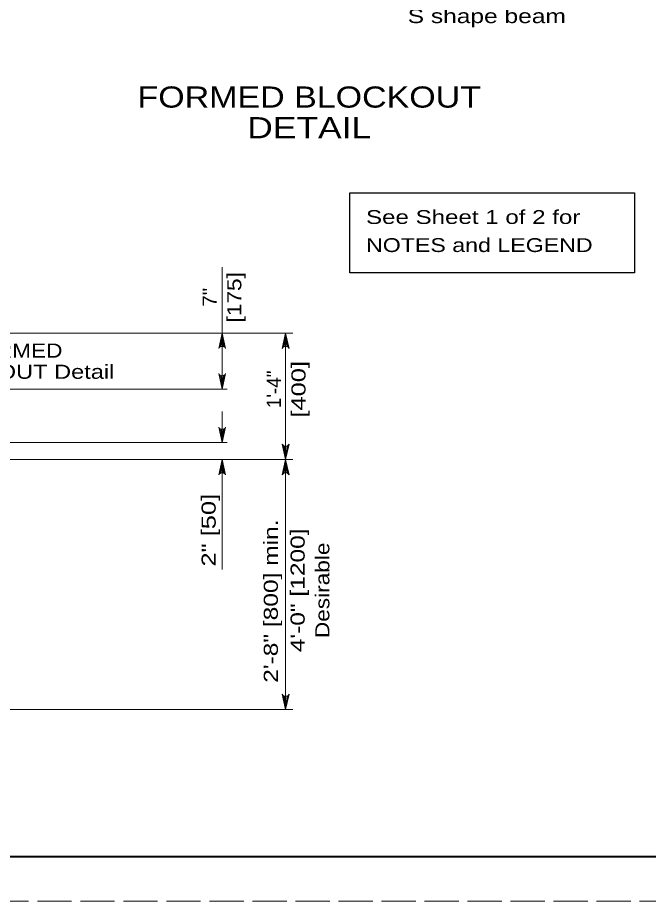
# Model space of a CAD drawing. Extents: x -1431.2 to -1397.2, y -1045.1 to -1001.1.
# Drawn here: x -1417.92 to -1410.82, y -1045.08 to -1035.13 of the extents above; entities that cross this region are included whole.
import ezdxf
from ezdxf.enums import TextEntityAlignment as Align

# ---------------------------------------------------------------- set-up
doc = ezdxf.new("R2010")
doc.units = 0
doc.header["$LTSCALE"] = 0.064
doc.linetypes.add('LONG_DASHED', pattern=[7.5, 6, -1.5])
doc.layers.add('1', color=7, linetype='Continuous', lineweight=13)

msp = doc.modelspace()

# ---------------------------------------------------------------- linework, layer by layer
at = {"layer": '1'}
for p, q in [((-1415.61583, -1039.31042), (-1415.61583, -1037.93983)), ((-1420.55817, -1038.68067), (-1414.82, -1038.68067)), ((-1415.61583, -1038.68067), (-1419.337, -1038.68067)), ((-1415.64275, -1038.83942), (-1415.61583, -1038.68067)), ((-1415.6315, -1038.83342), (-1415.61583, -1038.68067)), ((-1415.61583, -1038.83067), (-1415.61583, -1038.68067)), ((-1415.6035, -1038.83225), (-1415.61583, -1038.68067)), ((-1415.59142, -1038.83758), (-1415.61583, -1038.68067)), ((-1414.92833, -1038.83942), (-1414.90142, -1038.68067)), ((-1414.91708, -1038.83342), (-1414.90142, -1038.68067)), ((-1414.90142, -1038.83067), (-1414.90142, -1038.68067)), ((-1414.88908, -1038.83225), (-1414.90142, -1038.68067)), ((-1414.877, -1038.83758), (-1414.90142, -1038.68067)), ((-1414.90142, -1040.10408), (-1414.90142, -1038.68067)), ((-1415.64025, -1039.1535), (-1415.61583, -1039.31042)), ((-1415.62817, -1039.15883), (-1415.61583, -1039.31042)), ((-1415.58892, -1039.15167), (-1415.61583, -1039.31042)), ((-1415.60017, -1039.15767), (-1415.61583, -1039.31042)), ((-1415.61583, -1039.16042), (-1415.61583, -1039.31042)), ((-1421.27142, -1039.31042), (-1415.55833, -1039.31042)), ((-1415.61583, -1039.56333), (-1415.61583, -1039.91325)), ((-1415.64025, -1039.75642), (-1415.61583, -1039.91325)), ((-1415.62817, -1039.76167), (-1415.61583, -1039.91325)), ((-1415.58892, -1039.7545), (-1415.61583, -1039.91325)), ((-1415.60017, -1039.7605), (-1415.61583, -1039.91325)), ((-1415.61583, -1039.76333), (-1415.61583, -1039.91325)), ((-1420.77192, -1039.91325), (-1415.55833, -1039.91325)), ((-1414.92575, -1039.94717), (-1414.90142, -1040.10408)), ((-1414.91367, -1039.9525), (-1414.90142, -1040.10408)), ((-1414.87442, -1039.94533), (-1414.90142, -1040.10408)), ((-1414.88575, -1039.95133), (-1414.90142, -1040.10408)), ((-1414.90142, -1039.95417), (-1414.90142, -1040.10408)), ((-1420.562, -1040.10408), (-1414.82, -1040.10408)), ((-1415.64283, -1040.26283), (-1415.61583, -1040.10408)), ((-1415.6315, -1040.25683), (-1415.61583, -1040.10408)), ((-1415.61583, -1040.10408), (-1415.61583, -1041.34442)), ((-1415.61583, -1040.25408), (-1415.61583, -1040.10408)), ((-1415.6035, -1040.25567), (-1415.61583, -1040.10408)), ((-1415.59142, -1040.261), (-1415.61583, -1040.10408)), ((-1414.92833, -1040.26283), (-1414.90142, -1040.10408)), ((-1414.917, -1040.25683), (-1414.90142, -1040.10408)), ((-1414.90142, -1040.25408), (-1414.90142, -1040.10408)), ((-1414.88908, -1040.25567), (-1414.90142, -1040.10408)), ((-1414.877, -1040.261), (-1414.90142, -1040.10408)), ((-1414.90142, -1040.10408), (-1414.90142, -1042.9205)), ((-1414.92575, -1042.76358), (-1414.90142, -1042.9205)), ((-1414.91367, -1042.76892), (-1414.90142, -1042.9205)), ((-1414.87442, -1042.76175), (-1414.90142, -1042.9205)), ((-1414.88575, -1042.76775), (-1414.90142, -1042.9205)), ((-1414.90142, -1042.77058), (-1414.90142, -1042.9205)), ((-1420.564, -1042.9205), (-1414.82, -1042.9205))]:
    msp.add_line(p, q, dxfattribs=at)
at = {"layer": '1', "linetype": 'LONG_DASHED'}
msp.add_lwpolyline([(-1431.24575, -1045.07983), (-1397.24575, -1045.07983), (-1397.24575, -1023.07983), (-1431.24575, -1023.07983)], close=True, dxfattribs=at)
at = {"layer": '1', "lineweight": 25}
msp.add_lwpolyline([(-1397.74575, -1044.57983), (-1429.24575, -1044.57983), (-1429.24575, -1023.57983)], dxfattribs=at)
at = {"layer": '1', "lineweight": 40}
msp.add_lwpolyline([(-1429.24575, -1023.57983), (-1397.74575, -1023.57983), (-1397.74575, -1044.57983), (-1429.24575, -1044.57983)], close=True, dxfattribs=at)
at = {"layer": '1', "lineweight": 25}
msp.add_lwpolyline([(-1414.17792, -1037.10133), (-1410.97417, -1037.10133), (-1410.97417, -1038.00175), (-1414.17792, -1038.00175)], close=True, dxfattribs=at)
at = {"layer": '1'}
for points in [[(-1415.65433, -1038.854), (-1415.61583, -1038.68067), (-1415.57733, -1038.854)], [(-1414.93992, -1038.854), (-1414.90142, -1038.68067), (-1414.86292, -1038.854)], [(-1415.57733, -1039.13708), (-1415.61583, -1039.31042), (-1415.65433, -1039.13708)], [(-1415.57733, -1039.74), (-1415.61583, -1039.91325), (-1415.65433, -1039.74)], [(-1414.86283, -1039.93075), (-1414.90142, -1040.10408), (-1414.93992, -1039.93075)], [(-1415.65433, -1040.27742), (-1415.61583, -1040.10408), (-1415.57733, -1040.27742)], [(-1414.93992, -1040.27742), (-1414.90142, -1040.10408), (-1414.86283, -1040.27742)], [(-1414.86283, -1042.74725), (-1414.90142, -1042.9205), (-1414.93992, -1042.74725)]]:
    msp.add_lwpolyline(points, dxfattribs=at)
for centre, major_axis in [((-1415.61579, -1038.86798), (0.04156, 0)), ((-1414.90134, -1038.86798), (0.04156, 0)), ((-1415.61588, -1039.12309), (-0.04156, 0)), ((-1415.61588, -1039.72597), (-0.04156, 0)), ((-1414.90142, -1039.9168), (-0.04156, 0)), ((-1415.61579, -1040.2914), (0.04156, 0)), ((-1414.90134, -1040.2914), (0.04156, 0)), ((-1414.90142, -1042.73322), (-0.04156, 0))]:
    msp.add_ellipse(centre, major_axis=major_axis, ratio=0.9, start_param=0.3855052, end_param=2.7561184, dxfattribs=at)

# ---------------------------------------------------------------- texts
for s, height, width, p in [('S shape beam', 0.1588, 1.3, (-1413.52792, -1035.18958)), ('See Sheet 1 of 2 for', 0.156, 1.3, (-1413.99683, -1037.45158)), ('NOTES and LEGEND', 0.156, 1.25, (-1413.99683, -1037.76758)), ('See FORMED', 0.1588, 1.2, (-1419.04125, -1038.95708)), ('BLOCKOUT Detail', 0.1588, 1.25, (-1419.04125, -1039.19525))]:
    msp.add_text(s, height=height, dxfattribs=dict(at, width=width)).set_placement(p)
for s, width, p in [('FORMED BLOCKOUT', 1.2, (-1414.63592, -1036.14117)), ('DETAIL', 1.25, (-1414.63596, -1036.4865))]:
    msp.add_text(s, height=0.2382, dxfattribs=dict(at, width=width)).set_placement(p, align=Align.CENTER)
for s, width, p in [('[175]', 1.2, (-1415.4, -1038.27746)), ('7"', 1.1, (-1415.67783, -1038.27737)), ('[400]', 1.35, (-1414.67758, -1039.31371)), ('4\'-0" [1200]', 1.3, (-1414.68708, -1041.57742)), ('Desirable', 1.2, (-1414.40925, -1041.57738))]:
    msp.add_text(s, height=0.1588, rotation=90, dxfattribs=dict(at, width=width)).set_placement(p, align=Align.CENTER)
msp.add_text('1\'-4"', height=0.1588, rotation=90, dxfattribs=at).set_placement((-1414.95542, -1039.31379), align=Align.CENTER)
for s, width, p in [('2" [50]', 1.35, (-1415.68867, -1041.30992)), ('2\'-8" [800] min.', 1.3, (-1414.98883, -1042.61842))]:
    msp.add_text(s, height=0.1588, rotation=90, dxfattribs=dict(at, width=width)).set_placement(p)

doc.saveas('drawing.dxf')
